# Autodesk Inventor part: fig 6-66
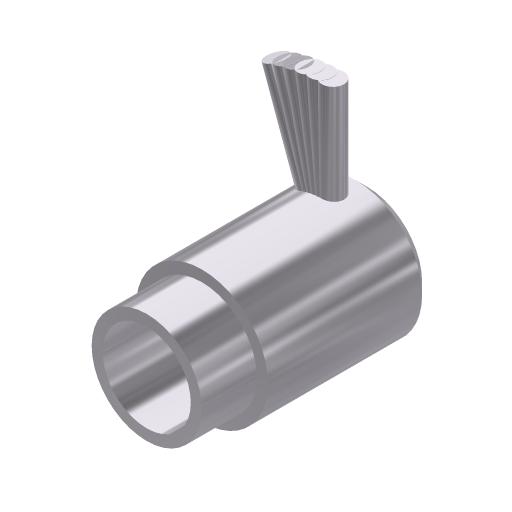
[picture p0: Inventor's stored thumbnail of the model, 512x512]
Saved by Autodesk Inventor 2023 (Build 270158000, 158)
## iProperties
Created: 2001-12
Part Number: fig 6-66
Document SubType Name: Modeling
Designer: Renu Muthoo
Density: 1 g/cm^3
Material: Generic
Appearance: Metal-AL-6061 (Polished)
Control State: 0
Master: False
Checked Out: False
Shininess: 77.0
Angle Display Precision: 2
Document Length Units: 11269
Document Angle Units: 11279
Document Time Units: 11290
Document Mass Units: 11283
Document Length Units Precision: 3
Document Angle Units Precision: 2
Compacted: True
Density: 0.0
Volumn: 0.0
Area: 0.0
PropertySet Name: Model Information
Author: Renu Muthoo
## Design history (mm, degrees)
sketch "Sketch2"
  geometry: L1 (-9.573, -4.327)-(-9.573, -5.327); L2 (-9.573, -5.327)-(-4.573, -5.327); L3 (-4.573, -5.327)-(-4.573, -6.327); L4 (-4.573, -6.327)-(9.427, -6.327); L5 (9.427, -6.327)-(10.427, -5.327); L6 (10.427, -5.327)-(10.427, -4.327); L7 (10.427, -4.327)-(-9.573, -4.327); L8 (-13.687, -0.327)-(14, -0.327)
  constraints: 16 end point, 5 parallel, 1 perpendicular, 1 vertical
  dimensions: "d9" = 20 distance of L6.end L1.start; "d10" = 5 distance of L1.end L2.end; "d11" = 12 diameter of L4 L8; "d12" = 10 diameter of L2 L8; "d13" = 8 diameter of L7 L8; "d14" = 45 deg angle of L5 L4; "d15" = 1 horizontal distance of L5.end L4.end
revolve "Revolution2" sketch "Sketch2" stored, may be unused: angle "d16" = 90 deg
workplane "Work Plane1"
workplane "Work Plane2"
sketch "Sketch3"
  geometry: L1 (-4, 8)-(4, 8) reference; C1 r 1 at (-0.098, 5)
  constraints: 1 centre point
  dimensions: "d18" = 3 distance from line of L1 C1.centre; "d19" = 2 diameter of C1
extrude "Extrusion1" join sketch "Sketch3" distance "d20" = 10; taper "d21" = 0 deg
pattern_circular "Circular Pattern3" dims angle "d29" = 20 deg
body "Solid1"
other parameters: "d17" = -1
